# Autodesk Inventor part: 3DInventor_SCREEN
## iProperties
Created: 2006-11
Part Number: 3DInventor_SCREEN
Document SubType Name: Modeling
Designer: conardl1
Density: 1 g/cm^3
DESCRIPTION: Screen Part
MODELED_BY: L Conard
Author: conardl1
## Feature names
1. Base1
